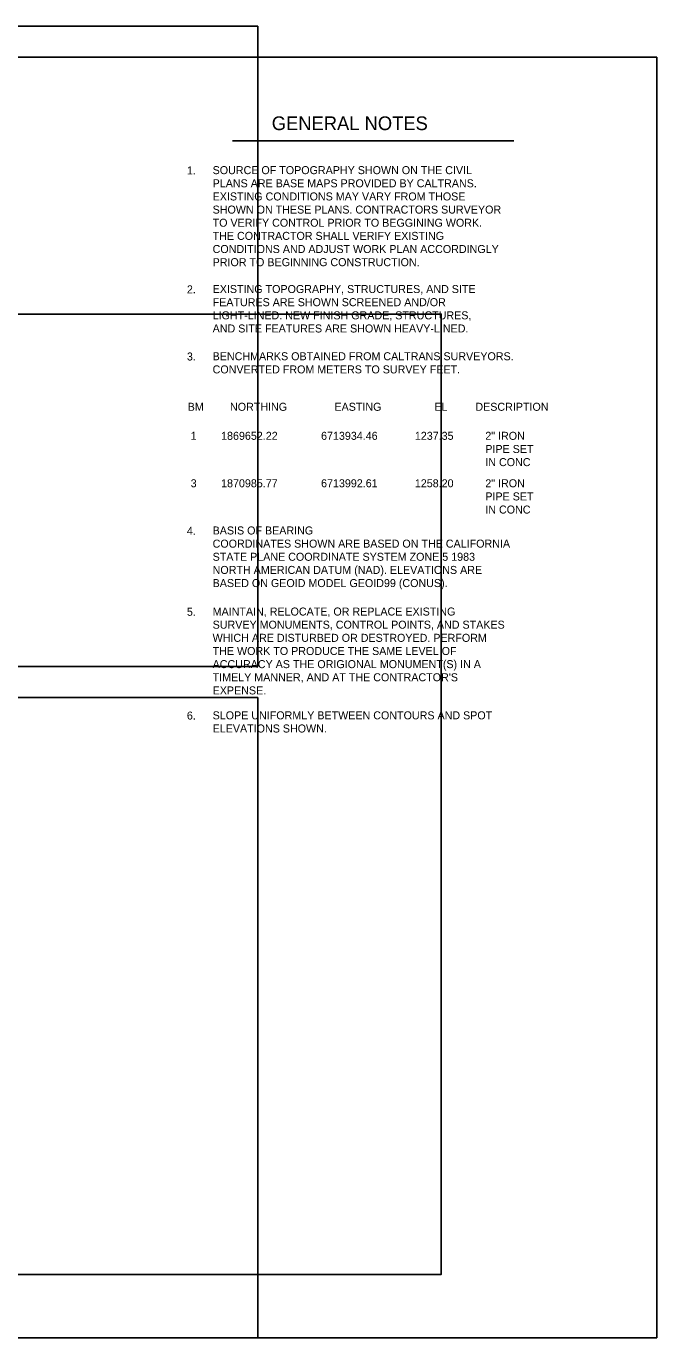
# Model space of a CAD drawing. Extents: x 6711682 to 6713077, y 1869209 to 1870525.
# Drawn here: x 6712525 to 6713077, y 1869377 to 1870525 of the extents above; entities that cross this region are included whole.
import ezdxf

# ---------------------------------------------------------------- set-up
doc = ezdxf.new("R2010")
doc.units = 0
for name, color, linetype in [('G-TTLB-VIEW', 7, 'Continuous'), ('Nongeo Data(60)', 7, 'Continuous'), ('Sheet Format(10)', 7, 'Continuous')]:
    doc.layers.add(name, color=color, linetype=linetype)

msp = doc.modelspace()

# ---------------------------------------------------------------- linework, layer by layer
at = {"layer": 'G-TTLB-VIEW'}
for points in [[(6712030.3, 1870524.7), (6712727.8, 1870524.7), (6712727.8, 1869964.7), (6712030.3, 1869964.7)], [(6711681.6, 1870497.5), (6713076.6, 1870497.5), (6713076.6, 1869377.5), (6711681.6, 1869377.5)], [(6711842, 1870272.9), (6712888.2, 1870272.9), (6712888.2, 1869432.8), (6711842, 1869432.8)], [(6712030.3, 1869937.5), (6712727.8, 1869937.5), (6712727.8, 1869377.5), (6712030.3, 1869377.5)]]:
    msp.add_lwpolyline(points, close=True, dxfattribs=at)
at = {"layer": 'Nongeo Data(60)'}
msp.add_line((6712705.8, 1870424.3), (6712951.5, 1870424.3), dxfattribs=at)

# ---------------------------------------------------------------- texts
msp.add_text('GENERAL NOTES', height=12, rotation=0, dxfattribs=at).set_placement((6712740, 1870433.8))
at = {"layer": 'Sheet Format(10)'}
for s, p in [('1.', (6712665.8, 1870395)), ('SOURCE OF TOPOGRAPHY SHOWN ON THE CIVIL', (6712688.3, 1870395.3)), ('PLANS ARE BASE MAPS PROVIDED BY CALTRANS.', (6712688.3, 1870383.8)), ('EXISTING CONDITIONS MAY VARY FROM THOSE', (6712688.3, 1870372.3)), ('SHOWN ON THESE PLANS. CONTRACTORS SURVEYOR', (6712688.3, 1870360.8)), ('TO VERIFY CONTROL PRIOR TO BEGGINING WORK.', (6712688.3, 1870349.3)), ('THE CONTRACTOR SHALL VERIFY EXISTING', (6712688.3, 1870337.8)), ('CONDITIONS AND ADJUST WORK PLAN ACCORDINGLY', (6712688.3, 1870326.3)), ('PRIOR TO BEGINNING CONSTRUCTION. ', (6712688.3, 1870314.8)), ('2.', (6712665.8, 1870291)), ('EXISTING TOPOGRAPHY, STRUCTURES, AND SITE', (6712688.3, 1870291.3)), ('FEATURES ARE SHOWN SCREENED AND/OR', (6712688.3, 1870279.8)), ('LIGHT-LINED. NEW FINISH GRADE, STRUCTURES,', (6712688.3, 1870268.3)), ('AND SITE FEATURES ARE SHOWN HEAVY-LINED.', (6712688.3, 1870256.8)), ('3.', (6712665.8, 1870232.3)), ('BENCHMARKS OBTAINED FROM CALTRANS SURVEYORS.', (6712688.3, 1870232.5)), ('CONVERTED FROM METERS TO SURVEY FEET.', (6712688.3, 1870221)), ('BM', (6712666.5, 1870188.3)), ('NORTHING', (6712703.5, 1870188.3)), ('EASTING', (6712794.8, 1870188.3)), ('EL', (6712882.1, 1870188.3)), ('DESCRIPTION', (6712918, 1870188.3)), ('1', (6712669.1, 1870162.9)), ('1869652.22', (6712695.7, 1870162.9)), ('6713934.46', (6712783.1, 1870162.9)), ('1237.35', (6712865.1, 1870162.9)), ('2" IRON', (6712926.7, 1870162.9)), ('PIPE SET', (6712926.7, 1870151.4)), ('IN CONC', (6712926.7, 1870139.9)), ('3', (6712669.1, 1870121.4)), ('1870985.77', (6712695.7, 1870121.4)), ('6713992.61', (6712783.1, 1870121.4)), ('1258.20', (6712865.1, 1870121.4)), ('2" IRON', (6712926.7, 1870121.4)), ('PIPE SET', (6712926.7, 1870109.9)), ('IN CONC', (6712926.7, 1870098.4)), ('4.', (6712665.8, 1870079.8)), ('BASIS OF BEARING', (6712688.3, 1870080.1)), ('COORDINATES SHOWN ARE BASED ON THE CALIFORNIA', (6712688.3, 1870068.6)), ('STATE PLANE COORDINATE SYSTEM ZONE 5 1983', (6712688.3, 1870057.1)), ('NORTH AMERICAN DATUM (NAD). ELEVATIONS ARE', (6712688.3, 1870045.6)), ('BASED ON GEOID MODEL GEOID99 (CONUS).', (6712688.3, 1870034.1)), ('5.', (6712665.8, 1870009)), ('MAINTAIN, RELOCATE, OR REPLACE EXISTING', (6712688.3, 1870009.2)), ('SURVEY MONUMENTS, CONTROL POINTS, AND STAKES', (6712688.3, 1869997.7)), ('WHICH ARE DISTURBED OR DESTROYED. PERFORM', (6712688.3, 1869986.2)), ('THE WORK TO PRODUCE THE SAME LEVEL OF', (6712688.3, 1869974.7)), ('ACCURACY AS THE ORIGIONAL MONUMENT(S) IN A', (6712688.3, 1869963.2)), ("TIMELY MANNER, AND AT THE CONTRACTOR'S", (6712688.3, 1869951.7)), ('EXPENSE.', (6712688.3, 1869940.2)), ('6.', (6712665.8, 1869918.2)), ('SLOPE UNIFORMLY BETWEEN CONTOURS AND SPOT', (6712688.3, 1869918.4)), ('ELEVATIONS SHOWN.', (6712688.3, 1869906.9))]:
    msp.add_text(s, height=7, dxfattribs=at).set_placement(p)

doc.saveas('drawing.dxf')
